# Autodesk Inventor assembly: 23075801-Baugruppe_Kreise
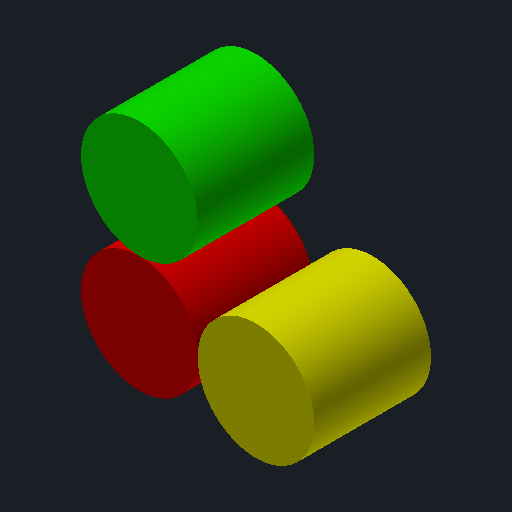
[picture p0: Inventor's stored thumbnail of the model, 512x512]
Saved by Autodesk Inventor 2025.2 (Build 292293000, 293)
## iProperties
Company: Ed. Züblin AG
Created: 2025-03
Part Number: 23075801-Baugruppe_Kreise
Material: Stahlbeton C30/37
Document SubType Name: Assembly
Designer: FrodlSte
Mass: 5.89049e+06 g
Surface Area: 141372 cm^2
Volume: 2.35619e+06 cm^3
Density: 2.5 g/cm^3
Description: Abdichtungstraeger
z_Bereich: Tunnelbau
z_Direktion: Tief- und Tunnelbau
z_Konzerneinheit: Zentrale Technik
cpiComponentType: Attribut
cpiFitMatchkey: =<z_Matchkey>
z_Matchkey: =<z_Matchkey_010>_<z_Matchkey_020>_<z_Matchkey_030>_<z_Matchkey_040>_<z_Matchkey_050>_<z_Matchkey_060>_<z_Matchkey_070>_<z_Matchkey_080>_<z_Matchkey_090>_<z_Mat
z_Matchkey_010: xxxxx
z_Matchkey_020: 5DTUB
z_Matchkey_030: xxx
z_Matchkey_040: xxx
z_Matchkey_050: xxx
z_Matchkey_060: xxx
z_Matchkey_070: xxx
z_Matchkey_080: xxx
z_Matchkey_090: xxx
z_Matchkey_100: xxx
z_Matchkey_110: xxx
z_Matchkey_120: xxxxxxx
z_Matchkey_130: xxxx
z_Matchkey_140: xxxx
DocNumber: 23075801-Baugruppe_Kreise.iam
Folder: DL23075801-DE-Pfaffensteigtunnel\BIM\Testmodell
VDS_Category: 09 - BIM - Konstruktion
Author: FrodlSte
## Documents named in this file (4)
- C:\z_Vault\CAD\DL23075801-DE-Pfaffensteigtunnel\BIM\Testmodell\23075801-Baugruppe_Kreise.iam
- C:\z_Vault\CAD\DL23075801-DE-Pfaffensteigtunnel\BIM\Testmodell\23075801-Kreis_1.ipt
- C:\z_Vault\CAD\DL23075801-DE-Pfaffensteigtunnel\BIM\Testmodell\23075801-Kreis_2.ipt
- C:\z_Vault\CAD\DL23075801-DE-Pfaffensteigtunnel\BIM\Testmodell\23075801-Kreis_3.ipt
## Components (3 placed, 3 different names)
1. 23075801-Kreis_1:1
2. 23075801-Kreis_2:1
3. 23075801-Kreis_3:1
